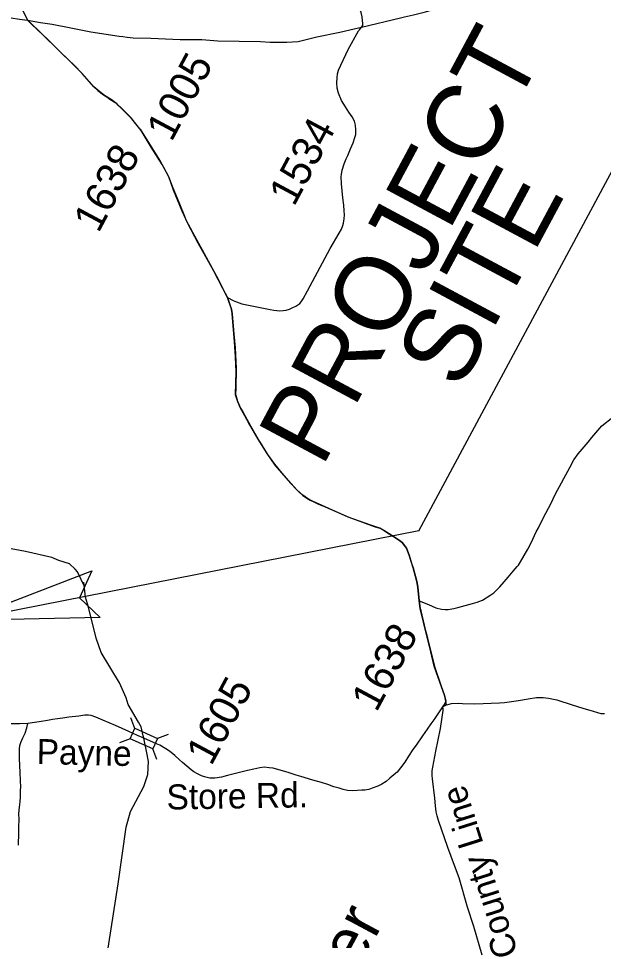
# Model space of a CAD drawing. Extents: x 1376167 to 1379209, y 761324 to 763997.
# Drawn here: x 1376526.6 to 1376608.1, y 762704.2 to 762832.7 of the extents above; entities that cross this region are included whole.
import ezdxf

# ---------------------------------------------------------------- set-up
doc = ezdxf.new("R2010")
doc.units = 0
doc.layers.add('Default', color=7, linetype='Continuous')
doc.layers.add('Old_Level_1', color=7, linetype='Continuous')

msp = doc.modelspace()

# ---------------------------------------------------------------- linework, layer by layer
at = {"layer": 'Default'}
for p, q in [((1376582.4, 762761.32), (1376614.56, 762821.29)), ((1376582.4, 762761.32), (1376518.9, 762748.79)), ((1376542.85, 762733.79), (1376542.29, 762735.26)), ((1376547.49, 762732.95), (1376546.01, 762732.39)), ((1376542.2, 762732.35), (1376540.72, 762731.79)), ((1376545.91, 762729.44), (1376545.35, 762730.92))]:
    msp.add_line(p, q, dxfattribs=at)
for points in [[(1376497.02, 762895.14), (1376527.9, 762832.44)], [(1376574.39, 762831.48), (1376574.57, 762831.71), (1376574.61, 762831.92), (1376574.49, 762832.91), (1376574.36, 762833.5), (1376574.22, 762833.85), (1376573.84, 762834.44), (1376573.53, 762834.81), (1376573.14, 762835.23), (1376572.52, 762835.66), (1376570.5, 762837.21), (1376567.13, 762839.67), (1376565.96, 762840.81), (1376565.78, 762841.11), (1376565.53, 762841.7), (1376565.39, 762842.29), (1376565.36, 762843.02), (1376565.39, 762843.64), (1376565.55, 762844.22), (1376566.09, 762845.52), (1376566.77, 762847.02), (1376567.16, 762847.79), (1376567.7, 762849.03)], [(1376574.39, 762831.48), (1376579.85, 762832.75), (1376580.41, 762832.9), (1376581.64, 762833.17), (1376582.76, 762833.45), (1376583.31, 762833.6), (1376584.11, 762833.81), (1376585.32, 762834.18), (1376586.42, 762834.49), (1376590.21, 762835.65), (1376594.03, 762836.84), (1376598.72, 762838.28), (1376599.2, 762838.44), (1376599.9, 762838.75)], [(1376524.07, 762833.11), (1376525.61, 762832.77), (1376526.77, 762832.56), (1376527.9, 762832.44)], [(1376556.95, 762783.46), (1376556.86, 762785.53), (1376556.74, 762787.63), (1376556.39, 762791.58), (1376556.3, 762792.16), (1376555.74, 762793.8), (1376553.81, 762797.57), (1376551.68, 762801.37), (1376550.22, 762804.09), (1376549.45, 762805.85), (1376548.23, 762808.76), (1376547.56, 762810.61), (1376546.65, 762812.33), (1376545.13, 762814.74), (1376543.71, 762817.06), (1376542.23, 762818.92), (1376540.98, 762820.18), (1376540.39, 762820.74), (1376539.67, 762821.27), (1376538.61, 762821.96), (1376537.68, 762822.68), (1376537.14, 762823.15), (1376535.49, 762825.01), (1376534.27, 762826.28), (1376527.92, 762832.42), (1376527.9, 762832.44)], [(1376527.9, 762832.44), (1376529.69, 762832.12), (1376531.35, 762831.86), (1376533.95, 762831.38), (1376536.73, 762830.8), (1376540.65, 762830.2), (1376541.16, 762830.14), (1376541.75, 762830.06), (1376542.6, 762829.98), (1376545.07, 762829.92), (1376549.15, 762829.74), (1376550.92, 762829.75), (1376552.15, 762829.72), (1376554.39, 762829.56), (1376560.32, 762829.46), (1376561.71, 762829.39)], [(1376527.9, 762832.44), (1376528.47, 762831.87), (1376529.35, 762831.04), (1376530.66, 762829.77), (1376531.37, 762829.09), (1376532.51, 762827.98), (1376534.53, 762826.01), (1376535.39, 762825.11), (1376537.2, 762823.09), (1376537.7, 762822.64), (1376538.5, 762822.04), (1376538.93, 762821.76), (1376539.38, 762821.43), (1376540.19, 762820.91), (1376540.44, 762820.66), (1376540.91, 762820.23), (1376541.74, 762819.4), (1376542.29, 762818.84), (1376542.91, 762818.05), (1376543.58, 762817.23), (1376544.4, 762815.92), (1376546.35, 762812.78), (1376546.84, 762811.97), (1376547.53, 762810.66), (1376548.02, 762809.29), (1376549.05, 762806.85), (1376549.68, 762805.35), (1376550, 762804.52), (1376551.44, 762801.86), (1376552.77, 762799.41), (1376554.49, 762796.26), (1376555.05, 762795.12), (1376555.74, 762793.79)], [(1376556.95, 762783.46), (1376556.86, 762785.53), (1376556.74, 762787.63), (1376556.39, 762791.58), (1376556.3, 762792.16), (1376555.74, 762793.8), (1376553.81, 762797.57), (1376551.68, 762801.37), (1376550.22, 762804.09), (1376549.45, 762805.85), (1376548.23, 762808.76), (1376547.56, 762810.61), (1376546.65, 762812.33), (1376545.13, 762814.74), (1376543.71, 762817.06), (1376542.23, 762818.92), (1376540.98, 762820.18), (1376540.39, 762820.74), (1376539.67, 762821.27), (1376538.61, 762821.96), (1376537.68, 762822.68), (1376537.14, 762823.15), (1376535.49, 762825.01), (1376534.27, 762826.28), (1376527.92, 762832.42), (1376527.9, 762832.44)], [(1376561.71, 762829.39), (1376564.03, 762829.35), (1376565.6, 762829.45), (1376568.18, 762830.11), (1376571.38, 762830.75), (1376573.37, 762831.21), (1376574.39, 762831.48)], [(1376566.89, 762794.73), (1376570.05, 762800.64), (1376571.31, 762802.75), (1376571.61, 762803.31), (1376571.82, 762803.85), (1376571.92, 762804.15), (1376572.01, 762804.75), (1376572.04, 762805.3), (1376572.01, 762805.88), (1376571.93, 762806.67), (1376571.8, 762807.7), (1376571.63, 762809.64), (1376571.59, 762810.67), (1376571.62, 762810.94), (1376571.7, 762811.55), (1376572, 762812.44), (1376572.27, 762813.12), (1376572.49, 762813.56), (1376572.88, 762814.5), (1376573.24, 762815.36), (1376573.49, 762816.11), (1376573.61, 762816.53), (1376573.63, 762817.16), (1376573.58, 762817.8), (1376573.44, 762818.35), (1376573.11, 762818.95), (1376572.63, 762819.64), (1376572.16, 762820.36), (1376571.61, 762821.24), (1376571.21, 762822.27), (1376571.04, 762822.97), (1376570.99, 762823.7), (1376571, 762824.42), (1376571.07, 762824.95), (1376571.21, 762825.49), (1376572.55, 762828.33), (1376574, 762830.93), (1376574.11, 762831.11), (1376574.39, 762831.48)], [(1376562.22, 762792.02), (1376563.04, 762791.96), (1376563.5, 762791.99), (1376563.93, 762792.04), (1376564.36, 762792.19), (1376564.86, 762792.39), (1376565.25, 762792.58), (1376565.81, 762792.96), (1376566.01, 762793.19), (1376566.28, 762793.61), (1376566.89, 762794.73)], [(1376555.74, 762793.79), (1376556.53, 762793.39), (1376556.99, 762793.18), (1376557.74, 762792.93), (1376561.7, 762792.12), (1376562.22, 762792.02)], [(1376555.74, 762793.79), (1376556.31, 762792.15), (1376556.39, 762791.55), (1376556.64, 762788.74), (1376556.8, 762786.77), (1376556.89, 762784.85), (1376556.93, 762784), (1376556.95, 762783.58), (1376556.95, 762783.46), (1376556.95, 762783.35), (1376556.94, 762783.17)], [(1376591.2, 762702.21), (1376590.06, 762706.18), (1376589.19, 762708.9), (1376588, 762712.96), (1376587.34, 762714.69), (1376586.44, 762717.2), (1376585.12, 762720.93), (1376584.93, 762721.61), (1376584.8, 762722.14), (1376584.74, 762722.57), (1376584.71, 762723.01), (1376584.6, 762724.04), (1376584.31, 762726.76), (1376584.27, 762727.22), (1376584.23, 762727.87), (1376584.35, 762728.38), (1376584.77, 762730.59), (1376585.4, 762733.79), (1376585.78, 762736.28), (1376585.77, 762736.6), (1376585.68, 762736.8), (1376586.26, 762737.05), (1376585.99, 762738.27), (1376585.09, 762740.89), (1376584.55, 762742.43), (1376584.07, 762744.46), (1376583.04, 762748.57), (1376582.6, 762750.5), (1376582.43, 762751.57), (1376582.25, 762753.46), (1376582.1, 762754.26), (1376581.58, 762756.14), (1376581.05, 762757.9), (1376580.66, 762758.89), (1376580.39, 762759.28), (1376580.06, 762759.68), (1376579.69, 762759.96), (1376578.64, 762760.66), (1376577.52, 762761.36), (1376576.97, 762761.66), (1376575.71, 762762.07), (1376572.55, 762763.22), (1376567.57, 762765.42), (1376566.87, 762765.82), (1376566.22, 762766.25), (1376565.41, 762767), (1376564.23, 762768.29), (1376562.38, 762770.46), (1376561.26, 762772.05), (1376560.01, 762774.06), (1376558.68, 762776.38), (1376557.94, 762777.72), (1376557.56, 762778.4), (1376557.19, 762779.28), (1376556.88, 762780.24), (1376556.95, 762783.46)], [(1376556.94, 762783.17), (1376556.92, 762781.92), (1376556.9, 762781.24), (1376556.88, 762780.24), (1376556.89, 762780.22), (1376557.15, 762779.37), (1376557.55, 762778.4), (1376557.86, 762777.86), (1376558.94, 762775.93), (1376560.2, 762773.75), (1376561.32, 762771.95), (1376562.27, 762770.61), (1376563.32, 762769.35), (1376564.54, 762767.96), (1376565.38, 762767.03), (1376565.68, 762766.74), (1376566.25, 762766.23), (1376566.79, 762765.87), (1376567.26, 762765.59), (1376567.77, 762765.33), (1376568.43, 762765.03), (1376569.35, 762764.63), (1376572.64, 762763.19), (1376574.54, 762762.5), (1376576.19, 762761.91), (1376576.97, 762761.66), (1376577.6, 762761.32), (1376578.27, 762760.88), (1376579.23, 762760.27), (1376579.69, 762759.96), (1376580.06, 762759.68), (1376580.39, 762759.28), (1376580.66, 762758.89), (1376581.05, 762757.9), (1376581.38, 762756.79), (1376581.58, 762756.14), (1376582.1, 762754.26), (1376582.25, 762753.46), (1376582.43, 762751.57)], [(1376582.43, 762751.56), (1376583.72, 762751.02), (1376584.77, 762750.58), (1376585.55, 762750.4), (1376586.07, 762750.35), (1376586.5, 762750.34), (1376587.27, 762750.5), (1376587.84, 762750.62), (1376588.86, 762750.9), (1376589.86, 762751.16), (1376590.52, 762751.36), (1376591.24, 762751.65), (1376592.44, 762752.39), (1376592.82, 762752.67), (1376593.68, 762753.51), (1376594.29, 762754.18), (1376594.84, 762754.87), (1376595.53, 762755.66), (1376596.09, 762756.31), (1376596.25, 762756.52), (1376596.53, 762756.97), (1376597.55, 762758.74), (1376598.03, 762759.65), (1376598.75, 762761.18), (1376599.05, 762761.7), (1376599.77, 762763.17), (1376600.76, 762765.06), (1376601.44, 762766.47), (1376603.4, 762770.13), (1376604, 762771.18), (1376604.58, 762772.01), (1376605.97, 762773.67), (1376606.5, 762774.29), (1376607.9, 762775.94), (1376609.4, 762777.14)], [(1376535.83, 762753.56), (1376534.84, 762755.58), (1376534.52, 762755.95), (1376533.75, 762756.69), (1376532.25, 762757.18), (1376531.28, 762757.6), (1376527.61, 762758.42), (1376524.88, 762758.91), (1376522.97, 762758.97), (1376515.83, 762758.59), (1376512.32, 762757.81), (1376510.71, 762758.22), (1376509.01, 762757.58), (1376507.14, 762755.67), (1376506.54, 762755.28), (1376505.35, 762754.75), (1376504.71, 762753.93), (1376504.47, 762752.63), (1376502.68, 762751.6)], [(1376543.98, 762732.74), (1376543.73, 762734.02), (1376543.37, 762734.66), (1376541.91, 762737.09), (1376541.63, 762738.02), (1376540.69, 762740.14), (1376538.15, 762744.35), (1376537.47, 762746.34), (1376536.41, 762750.66), (1376535.99, 762752.05), (1376535.74, 762754.13)], [(1376582.43, 762751.57), (1376582.6, 762750.5), (1376582.65, 762750.28), (1376582.66, 762750.23), (1376582.68, 762750.15), (1376582.72, 762749.99), (1376582.82, 762749.54), (1376583.34, 762747.37), (1376583.49, 762746.78), (1376583.52, 762746.67), (1376583.54, 762746.59), (1376583.56, 762746.51), (1376583.58, 762746.44), (1376583.59, 762746.37), (1376583.6, 762746.36), (1376584.07, 762744.48), (1376584.6, 762742.27), (1376585.47, 762739.78), (1376585.97, 762738.35), (1376586.14, 762737.57), (1376586.01, 762737.25)], [(1376586.26, 762737.05), (1376586.61, 762737.17), (1376586.92, 762737.23), (1376587.97, 762737.28), (1376588.49, 762737.27), (1376590.2, 762737.22), (1376593.64, 762737.34), (1376594.32, 762737.4), (1376596.25, 762737.66), (1376597.61, 762737.89), (1376598.78, 762738.07), (1376599.19, 762738.09), (1376599.73, 762738.08), (1376600.45, 762738.01), (1376601.6, 762737.76), (1376603.74, 762737.08), (1376605.23, 762736.6), (1376606.68, 762736.18), (1376607.28, 762735.99), (1376607.75, 762735.87), (1376608.27, 762735.85)], [(1376585.68, 762736.8), (1376584.85, 762735.52), (1376584.49, 762734.98), (1376584.06, 762734.42), (1376583.53, 762733.69), (1376582.9, 762732.73), (1376582.03, 762731.45), (1376581.57, 762730.86), (1376580.96, 762729.9), (1376580.42, 762729.1), (1376579.86, 762728.28), (1376579.36, 762727.69), (1376579.19, 762727.55), (1376578.37, 762726.83), (1376577.84, 762726.39), (1376577.22, 762726.01), (1376576.68, 762725.74), (1376575.89, 762725.46), (1376575.45, 762725.29), (1376574.87, 762725.19), (1376574.44, 762725.16), (1376573.22, 762725.1), (1376572.48, 762725.15), (1376571.84, 762725.29)], [(1376586.01, 762737.25), (1376585.68, 762736.8)], [(1376586.26, 762737.05), (1376586.01, 762737.25)], [(1376544.09, 762732.4), (1376543.22, 762732.8), (1376542.01, 762733.35), (1376540.13, 762734.19), (1376538.37, 762734.94), (1376537.43, 762735.34), (1376536.75, 762735.56), (1376536.39, 762735.61), (1376535.86, 762735.64), (1376535.06, 762735.49), (1376533.63, 762735.34), (1376532.81, 762735.21), (1376532.05, 762735.13), (1376531.37, 762735.01), (1376530.66, 762734.88), (1376529.52, 762734.69), (1376528.86, 762734.59), (1376527.93, 762734.45)], [(1376527.93, 762734.45), (1376526.78, 762734.42), (1376525.58, 762734.41)], [(1376526.63, 762717.52), (1376526.69, 762719.23), (1376526.68, 762720.07), (1376526.71, 762721.07), (1376526.69, 762721.94), (1376526.79, 762722.82), (1376526.85, 762723.57), (1376526.93, 762724.23), (1376526.92, 762725.06), (1376526.95, 762725.73), (1376526.93, 762726.38), (1376526.86, 762727.76), (1376526.81, 762728.49), (1376526.77, 762729.74), (1376526.77, 762730.45), (1376526.77, 762730.9), (1376526.83, 762731.38), (1376526.98, 762731.81), (1376527.25, 762732.45), (1376527.55, 762733.1), (1376527.8, 762733.84), (1376527.93, 762734.45)], [(1376544.09, 762732.4), (1376543.98, 762732.74)], [(1376538.3, 762696.72), (1376538.57, 762699.58), (1376540.51, 762712.13), (1376541.63, 762720.02), (1376542.23, 762722.22), (1376544.09, 762725.69), (1376544.64, 762727.35), (1376544.76, 762729.18), (1376544.46, 762730.61), (1376544.09, 762732.4)], [(1376571.84, 762725.29), (1376571.31, 762725.44), (1376570.57, 762725.66), (1376569.73, 762725.95), (1376568.86, 762726.23), (1376567.64, 762726.56), (1376565.96, 762727.09), (1376565.29, 762727.28), (1376564.32, 762727.61), (1376563.75, 762727.78), (1376562.89, 762728.03), (1376562.12, 762728.22), (1376561.54, 762728.31), (1376560.85, 762728.38), (1376560.24, 762728.29), (1376559.41, 762728.1), (1376558.51, 762727.91), (1376557.44, 762727.65), (1376556.69, 762727.47), (1376555.75, 762727.22), (1376554.9, 762726.99), (1376553.98, 762726.87), (1376553.83, 762726.87), (1376553.3, 762726.85), (1376552.54, 762727.04), (1376552.14, 762727.18), (1376551.58, 762727.44), (1376551.05, 762727.71), (1376550.69, 762728.01), (1376549.47, 762729.04), (1376549.06, 762729.39), (1376548.4, 762730), (1376547.69, 762730.6), (1376547.17, 762730.95), (1376546.34, 762731.43), (1376545.85, 762731.64), (1376544.09, 762732.4)]]:
    msp.add_lwpolyline(points, dxfattribs=at)
for points in [[(1376538.01, 762749.25), (1376518.9, 762748.79), (1376536.83, 762755.74), (1376535.12, 762751.99)], [(1376545.35, 762730.92), (1376542.2, 762732.34), (1376542.86, 762733.81), (1376546.01, 762732.39)]]:
    msp.add_lwpolyline(points, close=True, dxfattribs=at)

# ---------------------------------------------------------------- texts
at = {"layer": 'Old_Level_1'}
for s, height, rotation, p in [('PROJECT', 10.463, 61.8015, (1376568.91, 762769.99)), ('1005', 4.185, 61.8015, (1376547.95, 762815.36)), ('1534', 4.185, 61.8015, (1376565.01, 762806.35)), ('1638', 4.185, 61.8015, (1376537.78, 762802.67)), ('SITE', 10.463, 61.8015, (1376588.1, 762780.68)), ('1638', 4.185, 61.8015, (1376576.49, 762735.91)), ('1605', 4.185, 61.8015, (1376553.49, 762728.44)), ('Payne', 3.488, 358.7051, (1376529.14, 762728.83)), ('Store Rd.', 3.488, 0.9429, (1376547.28, 762722.47)), ('County Line', 3.4876, 107.5051, (1376596.26, 762702.41)), ('Alexander ', 6.539, 61.8015, (1376559.02, 762672.22))]:
    msp.add_text(s, height=height, rotation=rotation, dxfattribs=at).set_placement(p)

doc.saveas('drawing.dxf')
